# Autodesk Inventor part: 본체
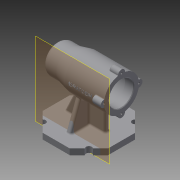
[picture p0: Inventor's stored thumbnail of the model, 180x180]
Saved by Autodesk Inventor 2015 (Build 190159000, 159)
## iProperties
Created: 2019-12
Part Number: 본체
Material: 일반
Document SubType Name: Modeling
Designer: now
Density: 1 g/cm^3
Appearance: 기본값
Author: now
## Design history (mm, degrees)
sketch "스케치1"
  geometry: L1 (56, 23.196)-(56, -23.196); L2 (56, -23.196)-(23.196, -56); L3 (23.196, -56)-(-23.196, -56); L4 (-23.196, -56)-(-56, -23.196); L5 (-56, -23.196)-(-56, 23.196); L6 (-56, 23.196)-(-23.196, 56); L7 (-23.196, 56)-(23.196, 56); L8 (23.196, 56)-(56, 23.196); C1 r 56 at (0, 0); 3 further points
  constraints: 16 end point, 2 coincident, 1 centre point, 1 midpoint, 1 tangent, 1 vertical alignment, 17 other
  dimensions: "d0" = 112 diameter of C1
extrude "돌출1" new body sketch "스케치1" distance "d1" = 10; taper "d2" = 0 deg
sketch "스케치2"
  geometry: L1 (-23.196, 56)-(-56, 23.196) reference; L2 (-56, -23.196)-(-23.196, -56) reference; L3 (23.196, -56)-(56, -23.196) reference; L4 (23.196, 56)-(56, 23.196) reference; C1 r 5 at (-39.598, 39.598); C2 r 5 at (39.598, 39.598); C3 r 5 at (39.598, -39.598); C4 r 5 at (-39.598, -39.598); 1 further point
  constraints: 4 centre point, 4 midpoint
  dimensions: "d3" = 10 diameter of C1; "d4" = 10 diameter of C2; "d5" = 10 diameter of C3; "d6" = 10 diameter of C4
extrude "돌출2" cut sketch "스케치2" distance "d7" = 10; taper "d8" = 0 deg
sketch "스케치3"
  geometry: L1 (56, -23.196)-(56, 23.196) reference; L2 (-56, 23.196)-(-56, -23.196) reference; L3 (-38, 4)-(31, 4); L4 (31, 4)-(31, -4); L5 (31, -4)-(-38, -4); L6 (-38, -4)-(-38, 4); 2 further points
  constraints: 8 end point, 2 parallel, 1 horizontal, 1 horizontal alignment, 1 midpoint, 1 perpendicular
  dimensions: "d9" = 18 distance from line of L2 point (-38, 0); "d10" = 25 distance between parallel lines of L1 L4; "d20" = 8 distance of L5.end L3.start
extrude "돌출3" join sketch "스케치3" distance "d11" = 70; taper "d12" = 0 deg
chamfer "모따기1" distance "d13" = 70; stored, may be unused: second distance "d14" = 2, angle "d15" = 25 deg
sketch "스케치4"
  geometry: L1 (-23.196, -56)-(23.196, -56) reference; L2 (4, 36)-(-4, 36); L3 (-4, 36)-(-4, -36); L4 (-4, -36)-(4, -36); L5 (4, -36)-(4, 36); L6 (4, 36)-(-4, -36); L7 (-4, 36)-(4, -36); 1 further point
  constraints: 12 end point, 2 midpoint, 2 parallel, 1 horizontal, 1 perpendicular
  dimensions: "d16" = 20 distance between parallel lines of L1 L4; "d17" = 8 distance of L3.end L4.end
extrude "돌출4" join sketch "스케치4" distance "d18" = 70; taper "d19" = 0 deg
chamfer "모따기2" distance "d21" = 70; stored, may be unused: second distance "d22" = 2, angle "d23" = 20 deg
chamfer "모따기3" distance "d24" = 70; stored, may be unused: second distance "d25" = 2, angle "d26" = 20 deg
sketch "스케치5"
  geometry: L1 (5.358, 80)-(38, 10) reference; L2 (38, 10)-(56, 10) reference; L3 (56, 10)-(56, 0) reference; L4 (56, 0)-(-56, 0) reference; L5 (-56, 0)-(-56, 10) reference; L6 (-56, 10)-(-31, 10) reference; L7 (-31, 10)-(-31, 80) reference; L8 (-31, 80)-(5.358, 80) reference; L9 (56, 80)-(-56, 80); L10 (-56, 80)-(-56, 110); L11 (-56, 110)-(11, 110); L12 (11, 110)-(31, 105); L13 (31, 105)-(56, 105); L14 (56, 105)-(56, 80); L15 (-4, 80)-(-31, 80) reference; 1 further point
  constraints: 12 end point, 3 perpendicular, 1 collinear, 1 horizontal, 1 parallel, 1 vertical alignment
  dimensions: "d27" = 112 distance of L9.start L9.end; "d28" = 30 distance of L9.end L10.end; "d29" = 25 distance of L13.end L9.start; "d30" = 25 distance of L12.end L13.end; "d31" = 45 distance from line of L14 L11.end
revolve "회전1" sketch "스케치5" stored, may be unused: angle "d32" = 90 deg
sketch "스케치6"
  geometry: C1 r 6 at (-30, 0); 2 further points
  constraints: 1 centre point, 1 horizontal alignment, 1 other
  dimensions: "d33" = 12 diameter of C1
extrude "돌출5" join sketch "스케치6" distance "d34" = 16; taper "d35" = 0 deg
sketch "스케치7"
  geometry: A1 r 6 centre (0, 0) between (0.6, 5.97) and (0.6, -5.97) reference; 1 further point
hole "구멍1" sketch "스케치7" at (0, 0) diameter "d39" = 3.242; stored, may be unused: countersink angle "d43" = 90 deg, drill point angle "d45" = 118 deg; dims "d40" = 8, "d41" = 4, "d42" = 2, "d44" = 11
sketch "스케치8"
  geometry: C1 r 21 at (30, 0); A1 r 30 centre (30, 0) between (0.6, -5.97) and (24.03, -29.4) reference; 1 further point
  constraints: 1 centre point, 1 coincident
  dimensions: "d49" = 42 diameter of C1
extrude "돌출6" cut sketch "스케치8" distance "d50" = 15; taper "d51" = 0 deg
sketch "스케치9"
  geometry: C1 r 21 at (0, 0) reference; C2 r 24 at (0, 0); 1 further point
  constraints: 1 centre point, 1 coincident
  dimensions: "d52" = 48 diameter of C2
extrude "돌출7" cut sketch "스케치9" distance "d53" = 54; taper "d54" = 0 deg
sketch "스케치10"
  geometry: C1 r 24 at (0, 0) reference; C2 r 21 at (0, 0); 1 further point
  constraints: 1 centre point, 1 coincident
  dimensions: "d55" = 42 diameter of C2
extrude "돌출8" cut sketch "스케치10" distance "d56" = 12; taper "d57" = 0 deg
sketch "스케치11"
  geometry: C1 r 21 at (0, 0) reference; C2 r 17.5 at (0, 0); 1 further point
  constraints: 1 centre point, 1 coincident
  dimensions: "d58" = 35 diameter of C2
extrude "돌출9" cut sketch "스케치11" distance "d59" = 18; taper "d60" = 0 deg
sketch "스케치12"
  geometry: C1 r 17.5 at (0, 0) reference; C2 r 16 at (0, 0); 1 further point
  constraints: 1 centre point, 1 coincident
  dimensions: "d61" = 32 diameter of C2
extrude "돌출10" cut sketch "스케치12" distance "d62" = 4; taper "d63" = 0 deg
sketch "스케치13"
  geometry: C1 r 16 at (0, 0) reference; C2 r 10.5 at (0, 0); 1 further point
  constraints: 1 centre point, 1 coincident
  dimensions: "d64" = 21 diameter of C2
extrude "돌출11" cut sketch "스케치13" distance "d65" = 3; taper "d66" = 0 deg
fillet "모깎기1" dims "d67" = 0.3
fillet "모깎기2" dims "d68" = 3
chamfer "모따기4" distance "d69" = 1; stored, may be unused: second distance "d70" = 2, angle "d71" = 20 deg
fillet "모깎기4" dims "d74" = 1, "d75" = 3
fillet "모깎기5" dims "d79" = 3
fillet "모깎기6" dims "d80" = 10
fillet "모깎기7" dims "d81" = 3
fillet "모깎기8" dims "d82" = 3
fillet "모깎기9" dims "d83" = 3
fillet "모깎기10" dims "d84" = 3
node "작업 평면1"
sketch "스케치14"
  geometry: L1 (56, 109.226)-(56, 86.771) reference; L2 (39, 110)-(-11, 110) reference; 2 further points
  constraints: 1 other
  dimensions: "d86" = 41 distance from line of L1 point (15, 80); "d90" = 30 distance from line of L2 point (15, 80)
feature "엠보싱1" sketch "스케치14" dims "d0" = 112, "d87" = 0.5, "d88" = 0
fillet "모깎기11" dims "d89" = 3
node "솔리드1"
pattern_circular "원형 패턴2" dims angle "d47" = 360 deg
pattern_circular "원형 패턴3" dims angle "d77" = 360 deg
node "절단 모서리 투영1"
